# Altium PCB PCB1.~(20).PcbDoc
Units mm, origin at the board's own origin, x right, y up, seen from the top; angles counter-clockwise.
Board outline 152.4 x 101.6 mm, 2 copper layers (Top Layer, Bottom Layer); 16 components, 6 nets, 37 pads, 0 vias.
Unrouted connection lines stored in the file: 1.
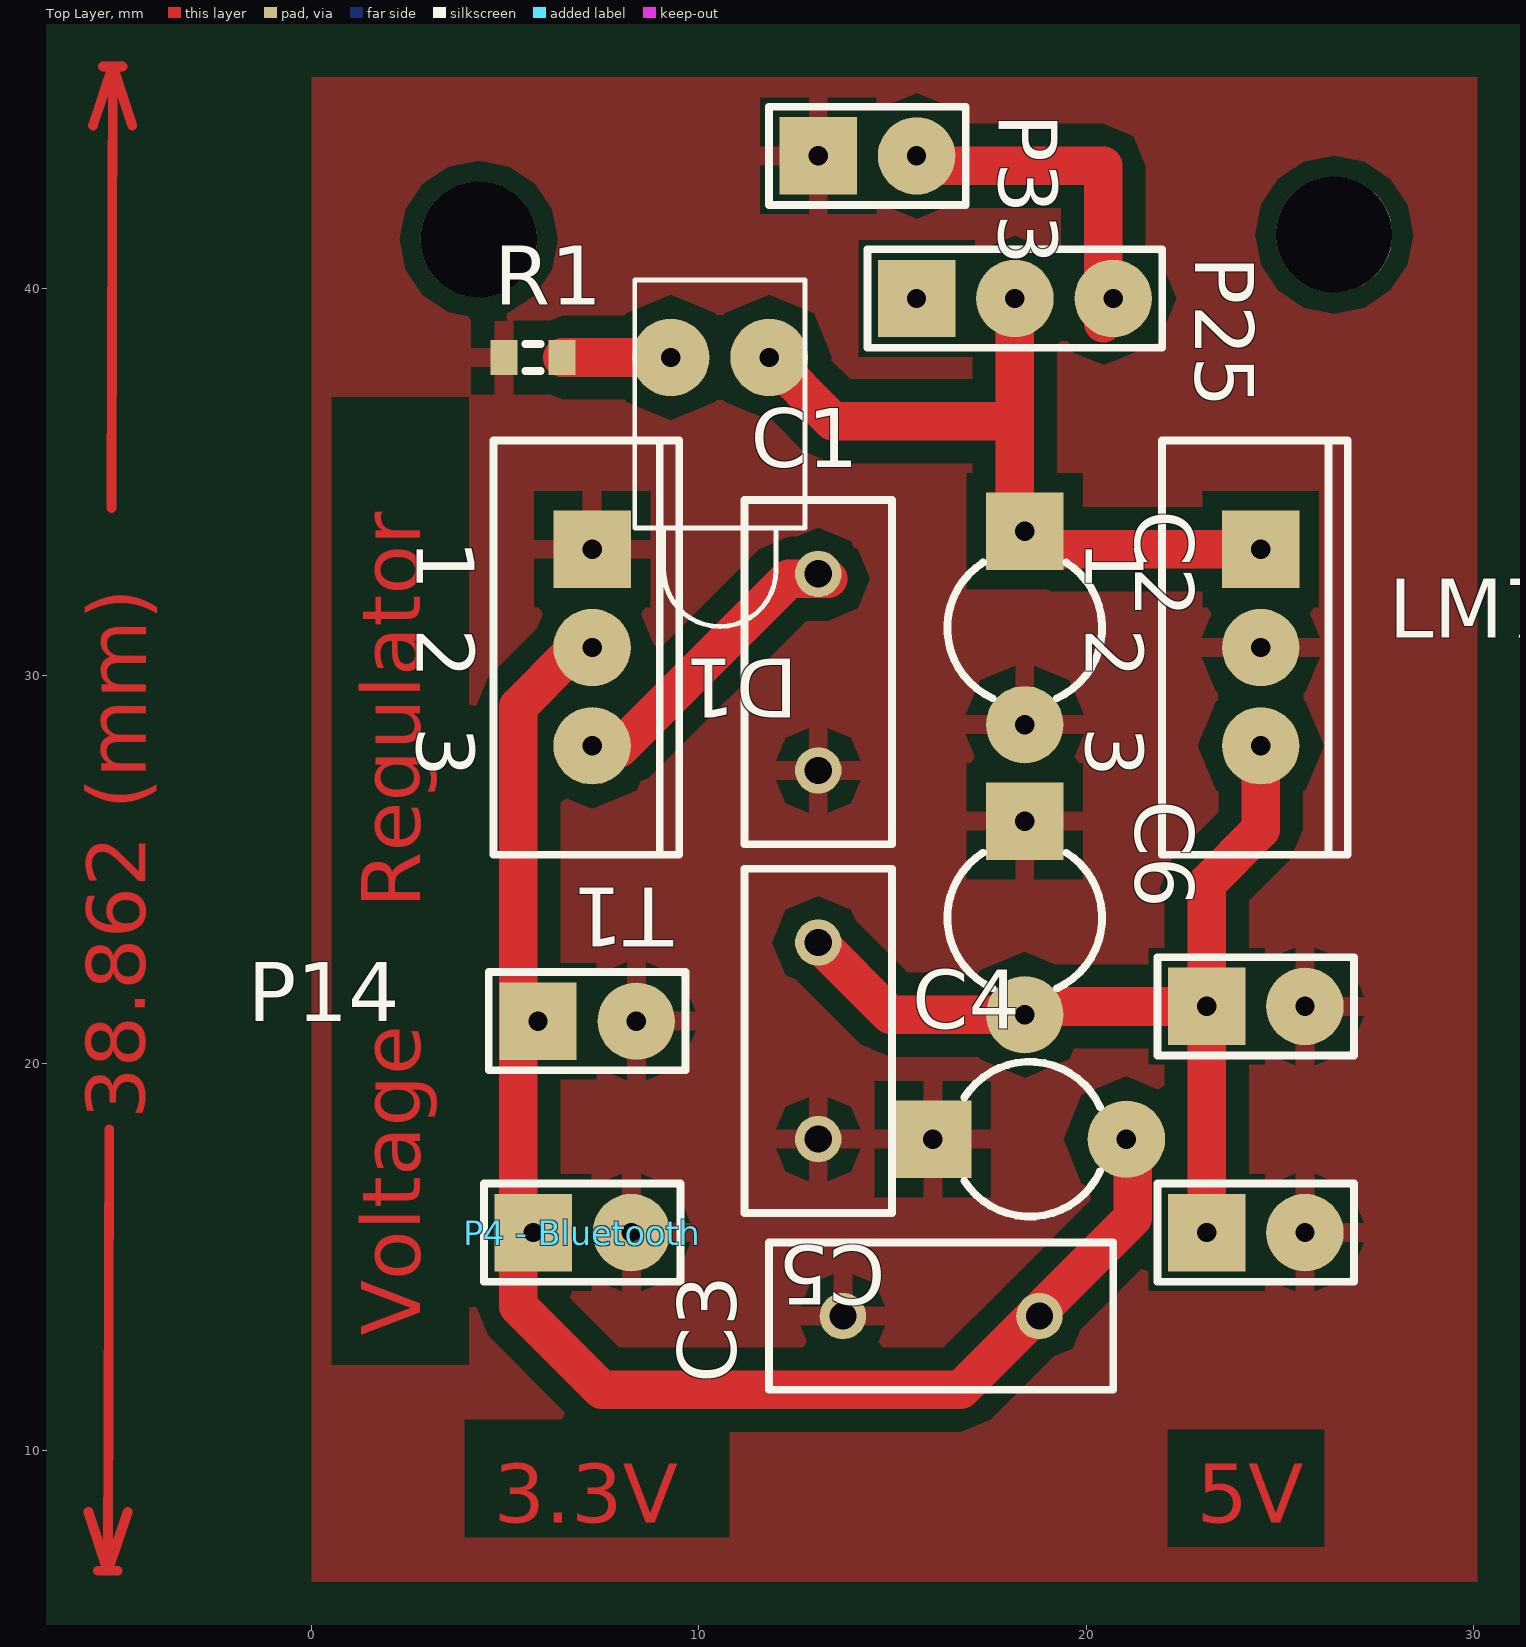
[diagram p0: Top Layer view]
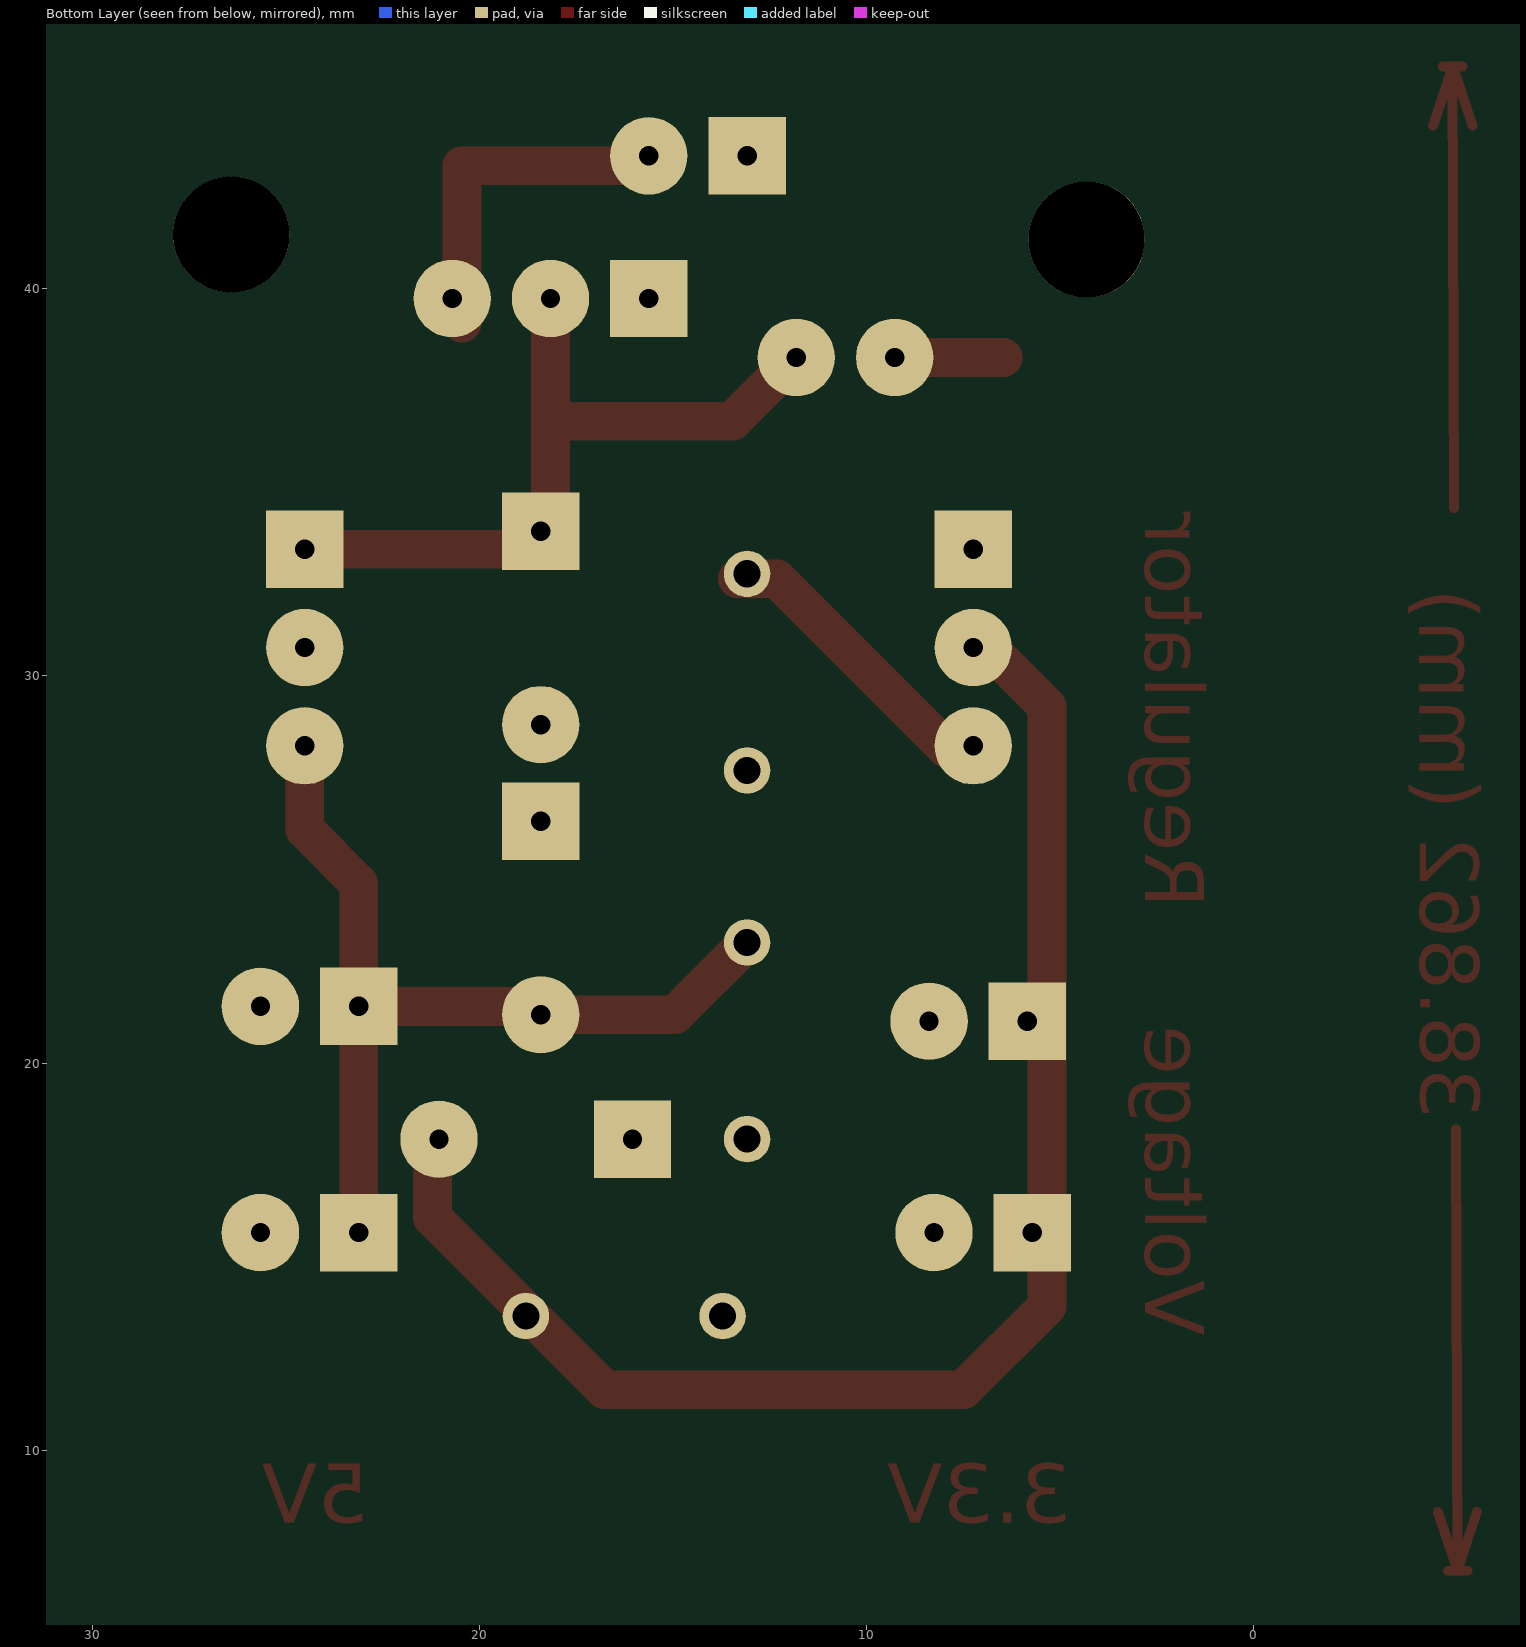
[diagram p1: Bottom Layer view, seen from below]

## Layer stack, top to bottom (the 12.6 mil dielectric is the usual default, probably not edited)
Top Layer: signal copper 0.0356
Dielectric: dielectric 0.32, FR-4, Dk 4.8
Bottom Layer: signal copper 0.0356

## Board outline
-90.043,-53.848 62.357,-53.848 62.357,47.752 -90.043,47.752

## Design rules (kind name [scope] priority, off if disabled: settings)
Clearance [All] p1: gap=0.5
PlaneClearance [All] p1: clearance=2
PolygonConnect [All] p1: connectstyle=Relief reliefconductorwidth=0.5 reliefentries=4 polygonreliefangle="90 Angle"
RoutingVias [All] p1: holewidth=0.711 width=1.27 viastyle="Through Hole" minholewidth=0.711 minwidth=1.27 maxholewidth=0.711 maxwidth=1.27
SilkscreenOverComponentPads [All] p1: minsilkscreentomaskgap=0.254
SolderMaskExpansion [All] p1: expansion=0.102
Width [All] p1: maxlimit=1 minlimit=0.5 preferedwidth=0.5
26 further rules are at their usual default settings.

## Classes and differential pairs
component class Sheet1: C1 C2 C3 C4 C5 C6 D1 LM7805 P14 P25 P33 R1 T1 ""

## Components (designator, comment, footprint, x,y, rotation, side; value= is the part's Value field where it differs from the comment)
C1 "Cap" RAD-0.2 13.081,30.099 r90 top
C2 "Cap2" CAPR5-4X5 18.415,31.242 r270 top
C3 "Cap" RAD-0.2 16.256,13.462 r180 top
C4 "Cap2" CAPR5-4X5 18.542,18.034 r0 top
C5 "Cap" RAD-0.2 13.081,20.574 r270 top
C6 "Cap2" CAPR5-4X5 18.415,23.749 r270 top
D1 "LED1" LED-1 10.541,38.227 r270 top
LM7805 "7805" TO-220-AB 24.511,30.734 r270 top locked
"P4 - Bluetooth" "Header 2" HDR1X2 5.715,15.621 r0 top
P10_S_Distancia "Header 2" HDR1X2 23.114,21.463 r0 top
P11_S_Distancia "Header 2" HDR1X2 23.114,15.621 r0 top
P14 "Header 2" HDR1X2 5.842,21.082 r0 top
P25 "Switch" HDR1X3 15.621,39.751 r0 top
P33 "Header 2" HDR1X2 13.081,43.434 r0 top
R1 "Res3" J1-0603 5.715,38.227 r0 top locked
T1 "LM1117" TO-220-AB 7.239,30.734 r270 top locked

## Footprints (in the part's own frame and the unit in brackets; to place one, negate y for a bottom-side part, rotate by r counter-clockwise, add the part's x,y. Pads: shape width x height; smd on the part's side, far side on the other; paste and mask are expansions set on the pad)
CAPR5-4X5 [mm] "Capacitor; 2 Leads"
  rect 2x2 hole 0.5: 1(-2.5,0)
  round 2 hole 0.5: 2(2.5,0)
  silkscreen extent -1.69,-2 1.82,2
HDR1X2 [mm] "Connector; Header; 2 Position"
  rect 2x2 hole 0.5: 1(0,0)
  round 2 hole 0.5: 2(2.54,0)
  silkscreen extent -1.27,-1.27 3.81,1.27
HDR1X3 [mm] "Connector; Header; 3 Position"
  rect 2x2 hole 0.5: 1(0,0)
  round 2 hole 0.5: 2(2.54,0) 3(5.08,0)
  silkscreen extent -1.27,-1.27 6.35,1.27
J1-0603 [mm] "Chip Resistor, Body 1.6x0.8mm, IPC High Density"
  rect 0.7x0.9 smd: 1(-0.75,0) 2(0.75,0)
  silkscreen extent -0.2,-0.35 0.2,0.35, body extent -0.85,-0.48 0.85,0.48, height 0.9
LED-1 [mm] "LED; 2 Leads"
  round 2 hole 0.5: 1(0,1.27) 2(0,-1.27)
  silkscreen extent -2,-2.2 6.95,2.2
RAD-0.2 [mm] "Radial Cap, Thru-Hole; 2 Leads; 0.2 in Pin Spacing"
  round 1.2 hole 0.7: 1(-2.54,0) 2(2.54,0)
  silkscreen extent -4.44,-1.91 4.44,1.91
TO-220-AB [mm] "TO, Thru-Hole, Vertical, Heatsink Mounted; 3 In-Line Leads; Pitch 2.54 mm"
  rect 2x2 hole 0.5: 1(-2.54,0)
  round 2 hole 0.5: 2(0,0) 3(2.54,0)
  silkscreen extent -5.35,-2.55 5.35,2.25

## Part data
C1 C2 C3 C4 C5 C6: "Capacitor"
D1: "Typical RED GaAs LED"
LM7805 T1: library part 2N3906, "PNP General Purpose Amplifier"
"P4 - Bluetooth" P10_S_Distancia P11_S_Distancia P14 P33: "Header, 2-Pin"
P25: library part "Header 3", "Header, 3-Pin"
R1: "Resistor"

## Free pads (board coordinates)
  round 3 hole 3: 0(4.311,41.275) 0(26.409,41.402)

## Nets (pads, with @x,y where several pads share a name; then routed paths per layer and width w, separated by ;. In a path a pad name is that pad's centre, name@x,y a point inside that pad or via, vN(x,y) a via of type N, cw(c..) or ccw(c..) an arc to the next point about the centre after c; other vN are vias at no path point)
GND: "P4 - Bluetooth.2" C1.1 C2.2 C3.2 C4.1 C5.2 C6.1 LM7805.2 P10_S_Distancia.2 P11_S_Distancia.2 P14.2 P33.1 R1.1 T1.1
NetC1_2: C1.2 C2.1 D1.1 LM7805.1 P25.2 T1.3 | length 25.9
  Top Layer w1: T1.3@7.938,28.13 12.319,32.512 C1.2@13.335,32.512 ; D1.1 13.462,36.576 18.161,36.576 ; P25.2@18.161,39.116 18.161,36.576 ; LM7805.1 19.09,33.274 18.161,34.203 18.161,36.576
NetC3_1: "P4 - Bluetooth.1" C3.1 C4.2 P14.1 T1.2 | length 38.7
  Top Layer w1: T1.2@7.429,30.543 6.667,30.543 5.334,29.21 5.334,13.716 7.493,11.557 16.764,11.557 21.209,16.002 C4.2@21.209,17.907
NetC5_1: C5.1 C6.2 LM7805.3 P10_S_Distancia.1 P11_S_Distancia.1 | length 24.2
  Top Layer w1: C5.1 14.946,21.249 C6.2 18.629,21.463 P10_S_Distancia.1 ; P11_S_Distancia.1 P10_S_Distancia.1 ; P10_S_Distancia.1@23.241,21.463 P10_S_Distancia.1 ; LM7805.3 24.511,26.035 23.114,24.638 P10_S_Distancia.1
NetD1_2: D1.2 R1.2 | length 2.7
  Top Layer w1: R1.2 D1.2@9.172,38.227
NetP25_3: P25.3 P33.2 | length 8.9
  Top Layer w1: P33.2@15.621,43.18 20.447,43.18 P25.3@20.447,39.116
pads on no net: P25.1
copper on no net: | length 30.3
  Top Layer w0.254: -5.773,8.41 -5.27,6.884 ; -5.656,44.224 -5.143,45.746 ; -5.524,6.885 -5.016,6.883 ; -5.397,45.747 -4.889,45.745 ; -5.233,18.291 -5.27,6.884 ; -5.181,34.339 -5.143,45.746 ; -4.757,8.406 -5.27,6.884 ; -4.64,44.22 -5.143,45.746

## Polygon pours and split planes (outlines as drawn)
GND on Top Layer "Top Layer-No Net" (solid, pour order 2): 0,45.466 30.099,45.466 30.099,6.604 0,6.604

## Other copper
Top Layer:
  text "Regulator" at 2.794,24.003 h1.52 r90
  text "38.862 (mm)" at -4.318,18.542 h1.52 r89.81
  text "Voltage" at 2.794,12.954 h1.52 r90
  text "3.3V" at 4.699,8.128 h1.52
  text "5V" at 22.86,8.128 h1.52

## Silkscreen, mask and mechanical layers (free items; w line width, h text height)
Mechanical 1:
  lines w0.254: -0.129,46.736 -0.125,46.228 ; 1.393,47.003 -0.127,46.482 ; 1.401,45.987 -0.127,46.482 ; 6.962,46.542 -0.127,46.482 ; 23.01,46.676 30.099,46.736 ; 28.571,47.231 30.099,46.736 ; 28.579,46.215 30.099,46.736 ; 30.097,46.99 30.101,46.482
  text "30.227 (mm)" at 7.224,45.63 h1.52 r0.48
